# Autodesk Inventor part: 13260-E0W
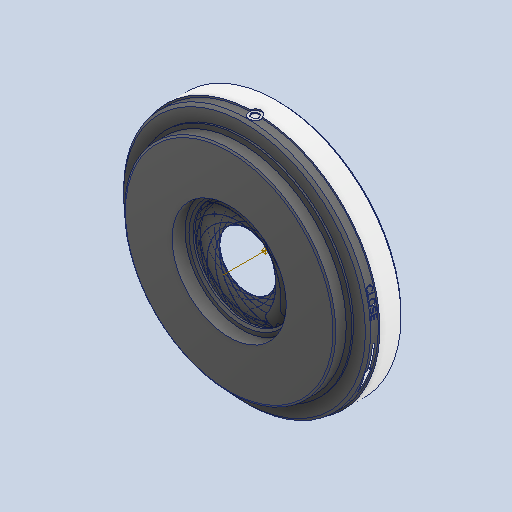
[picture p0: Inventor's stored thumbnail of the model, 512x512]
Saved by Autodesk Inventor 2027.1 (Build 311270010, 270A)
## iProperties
Created: 2023-02
Part Number: 13260-E0W
Material: Generic
Description: STEP AP214
Document SubType Name: Modeling
Designer: dunge
Density: 1 g/cm^3
Appearance: Default
Title: 13260-E0W.STEP
Revision Number: ANY
Sending System: SolidWorks 2022
Preprocessor: SwSTEP 2.0
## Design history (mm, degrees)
feature "13260-001-1-solid1"
feature "0595-999-1_700-370 Outer Ring-1-solid1"
feature "0595-999-1_700-370 Inner Ring-1-solid1"
feature "0595-999-1_700-370 Blade-1-solid1"
feature "0595-999-1_700-370 Blade-2-solid1"
feature "0595-999-1_700-370 Blade-3-solid1"
feature "0595-999-1_700-370 Blade-4-solid1"
feature "0595-999-1_700-370 Blade-5-solid1"
feature "0595-999-1_700-370 Blade-6-solid1"
feature "0595-999-1_700-198 Lever-1-solid1"
feature "0595-999-1_700-370 Blade-7-solid1"
feature "0595-999-1_700-370 Blade-8-solid1"
feature "0595-999-1_700-370 Blade-9-solid1"
feature "0595-999-1_700-370 Blade-10-solid1"
feature "0595-999-1_700-370 Blade-11-solid1"
feature "0595-999-1_700-370 Blade-12-solid1"
feature "0595-999-1_700-370 Blade-13-solid1"
feature "0595-999-1_700-370 Blade-14-solid1"
feature "13260-002-1-solid1"
feature "13260-003-1-solid1"
feature "SS4A013-1-1-solid1"
workpoint "Work Point1"
  workaxis "Work Axis1"
body "Solid1"
body "Solid2"
body "Solid3"
body "Solid4"
body "Solid5"
body "Solid6"
body "Solid7"
body "Solid8"
body "Solid9"
body "Solid10"
body "Solid11"
body "Solid12"
body "Solid13"
body "Solid14"
body "Solid15"
body "Solid16"
body "Solid17"
body "Solid18"
body "Solid19"
body "Solid20"
body "Solid21"
